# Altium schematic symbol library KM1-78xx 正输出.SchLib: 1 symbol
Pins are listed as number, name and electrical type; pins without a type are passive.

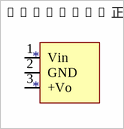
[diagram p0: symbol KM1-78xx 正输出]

## KM1-78xx 正输出
designator *
footprint Model Name (Footprint not found)
pins: 1 Vin, 2 GND, 3 +Vo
